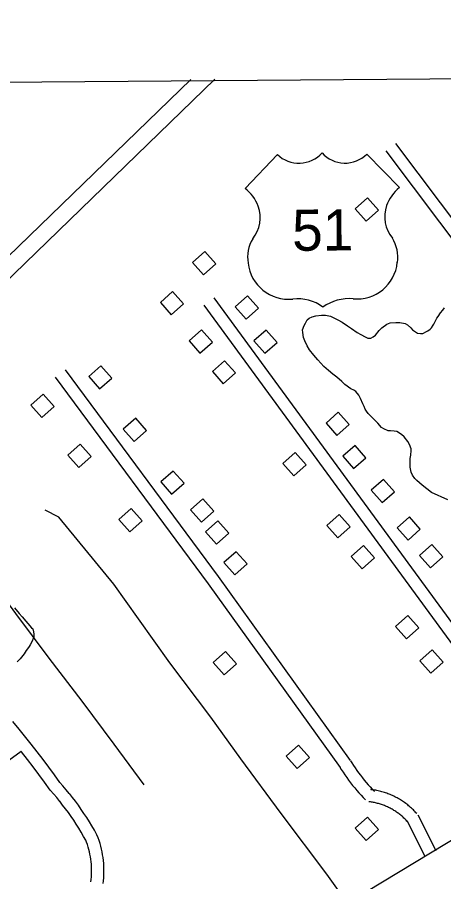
# Model space of a CAD drawing. Extents: x 3540316 to 3578335, y 553172 to 578787.
# Drawn here: x 3555638 to 3556674, y 574901 to 577000 of the extents above; entities that cross this region are included whole.
import ezdxf

# ---------------------------------------------------------------- set-up
doc = ezdxf.new("R2010")
doc.units = 0
for name, color, linetype in [('V-BLDG-OTLN', 7, 'Continuous'), ('V-GRID-FRAM', 7, 'Continuous'), ('V-ROAD-CNTR', 7, 'Continuous'), ('V-ROAD-IDEN', 7, 'Continuous'), ('V-SITE-VEGE', 7, 'Continuous'), ('V-TOPO-SHOR', 7, 'Continuous')]:
    doc.layers.add(name, color=color, linetype=linetype)

msp = doc.modelspace()

# ---------------------------------------------------------------- linework, layer by layer
at = {"layer": 'V-BLDG-OTLN'}
for points in [[(3556485.3, 576504.7), (3556515.2, 576531.2), (3556488.7, 576561.1), (3556458.7, 576534.6)], [(3556090.4, 576374.5), (3556120.4, 576401), (3556093.8, 576430.9), (3556063.9, 576404.4)], [(3556012.1, 576277.5), (3556042, 576304.1), (3556015.4, 576334), (3555985.5, 576307.5)], [(3556193.9, 576266.8), (3556223.9, 576293.3), (3556197.3, 576323.2), (3556167.4, 576296.7)], [(3556081.8, 576184.3), (3556111.8, 576210.8), (3556085.2, 576240.7), (3556055.3, 576214.2)], [(3556238.9, 576183.9), (3556268.8, 576210.4), (3556242.3, 576240.4), (3556212.3, 576213.8)], [(3556138.3, 576109.5), (3556168.3, 576136.1), (3556141.7, 576166), (3556111.8, 576139.5)], [(3555838, 576097.4), (3555867.9, 576123.9), (3555841.4, 576153.8), (3555811.5, 576127.3)], [(3555697.9, 576028), (3555727.8, 576054.5), (3555701.3, 576084.5), (3555671.3, 576057.9)], [(3556414.3, 575984.3), (3556444.2, 576010.8), (3556417.7, 576040.7), (3556387.8, 576014.2)], [(3555922.2, 575969.9), (3555952.1, 575996.4), (3555925.6, 576026.4), (3555895.6, 575999.8)], [(3555787.4, 575906.5), (3555817.3, 575933), (3555790.8, 575962.9), (3555760.8, 575936.4)], [(3556454.9, 575903.8), (3556484.9, 575930.4), (3556458.3, 575960.3), (3556428.4, 575933.8)], [(3556309.8, 575886.7), (3556339.7, 575913.2), (3556313.2, 575943.2), (3556283.2, 575916.6)], [(3556013, 575841.7), (3556043, 575868.2), (3556016.4, 575898.1), (3555986.5, 575871.6)], [(3556523.9, 575821.3), (3556553.8, 575847.9), (3556527.3, 575877.8), (3556497.3, 575851.3)], [(3556085.4, 575773.7), (3556115.4, 575800.3), (3556088.8, 575830.2), (3556058.9, 575803.7)], [(3555911.2, 575750.3), (3555941.1, 575776.9), (3555914.6, 575806.8), (3555884.7, 575780.3)], [(3556416.6, 575736.2), (3556446.6, 575762.7), (3556420, 575792.6), (3556390.1, 575766.1)], [(3556586.9, 575730.5), (3556616.8, 575757), (3556590.3, 575786.9), (3556560.4, 575760.4)], [(3556121.7, 575720.5), (3556151.6, 575747), (3556125.1, 575777), (3556095.2, 575750.4)], [(3556166.1, 575645.7), (3556196, 575672.3), (3556169.5, 575702.2), (3556139.5, 575675.7)], [(3556475.6, 575660.6), (3556505.5, 575687.2), (3556479, 575717.1), (3556449, 575690.6)], [(3556641.5, 575663.3), (3556671.4, 575689.8), (3556644.9, 575719.7), (3556615, 575693.2)], [(3556583.3, 575490.4), (3556613.2, 575516.9), (3556586.7, 575546.9), (3556556.7, 575520.3)], [(3556140.7, 575403.5), (3556170.6, 575430), (3556144, 575459.9), (3556114.1, 575433.4)], [(3556642.2, 575407.3), (3556672.2, 575433.9), (3556645.6, 575463.8), (3556615.7, 575437.3)], [(3556317.8, 575175.8), (3556347.7, 575202.3), (3556321.2, 575232.3), (3556291.2, 575205.7)], [(3556485, 575000.9), (3556514.9, 575027.5), (3556488.4, 575057.4), (3556458.5, 575030.8)]]:
    msp.add_lwpolyline(points, close=True, dxfattribs=at)
at = {"layer": 'V-GRID-FRAM'}
for points in [[(3544387.2, 576756), (3576013, 576999.8), (3576161.1, 558817.2), (3544519.4, 558573.3), (3544387.2, 576756)], [(3544387.2, 576756), (3576013, 576999.8)]]:
    msp.add_lwpolyline(points, dxfattribs=at)
at = {"layer": 'V-ROAD-CNTR'}
for points in [[(3556059.6, 576849.1), (3555248.7, 576063.5), (3553492.5, 574335)], [(3556117.7, 576849.5), (3555276.7, 576034.8), (3553520.7, 574306.4)], [(3557474.2, 575475.1), (3556557.5, 576693.2)], [(3557448.5, 575459.5), (3556533.5, 576675.2)], [(3556115.3, 576318.4), (3556960.7, 575164.1)], [(3556091.1, 576300.7), (3556936.5, 575146.3)], [(3555754.2, 576143.7), (3556126.1, 575641.7), (3556446.5, 575195.3)], [(3555730.1, 576125.8), (3556101.9, 575624), (3556422.1, 575177.8)], [(3558125.7, 575871.4), (3557699.7, 575612.4), (3556948.6, 575155.2), (3555833.4, 574482.3)], [(3555872.2, 575623.6), (3555739.2, 575785.8), (3555706.2, 575803)], [(3556440.2, 574848.4), (3556389.8, 574919), (3556278.9, 575066.4), (3556181.3, 575199.2), (3556108.4, 575300.5), (3556008.4, 575432.1), (3555932.5, 575539.3), (3555872.2, 575623.6)], [(3555764.5, 575115), (3555756.9, 575124.2), (3555749.1, 575133.3), (3555741.8, 575141.6), (3555728.5, 575160), (3555714.6, 575178.8), (3555700.6, 575197.6), (3555686.4, 575216.3), (3555672, 575234.8), (3555662.1, 575247.2), (3555642.7, 575271.4), (3555627.7, 575289.5)], [(3555647.6, 575217.2), (3555617.5, 575195.2), (3555575.7, 575164.7), (3555533.8, 575134.4), (3555491.7, 575104.3), (3555465.2, 575085.2)], [(3555741.3, 575095.9), (3555733.9, 575104.9), (3555726.5, 575113.6), (3555718.3, 575122.8), (3555704.3, 575142.3), (3555690.5, 575161), (3555676.7, 575179.5), (3555662.6, 575197.9), (3555648.4, 575216.2), (3555647.1, 575217.8)], [(3556421.5, 575178.7), (3556425, 575173.1), (3556429.3, 575166.5), (3556433.7, 575160), (3556438.2, 575153.6), (3556442.8, 575147.2), (3556447.6, 575140.8), (3556452.5, 575134.6), (3556457.4, 575128.5), (3556462.5, 575122.5), (3556467.7, 575116.5), (3556473, 575110.7), (3556478.4, 575104.9), (3556483.8, 575099.3)], [(3556447, 575194.5), (3556450.2, 575189.3), (3556454.3, 575183.1), (3556458.4, 575177), (3556462.7, 575171), (3556467, 575165), (3556471.4, 575159.2), (3556476, 575153.3), (3556480.6, 575147.6), (3556485.3, 575142), (3556490.2, 575136.4), (3556495.1, 575130.9), (3556500.1, 575125.5), (3556505.3, 575120.2)], [(3555846.6, 574896.2), (3555847.4, 574903.2), (3555848.1, 574910.2), (3555848.5, 574917.2), (3555848.7, 574924.3), (3555848.7, 574931.3), (3555848.5, 574938.3), (3555848, 574945.4), (3555847.4, 574952.4), (3555846.5, 574959.4), (3555845.4, 574966.4), (3555844.1, 574973.3), (3555842.6, 574980.2), (3555840.9, 574987), (3555839, 574993.8), (3555836.8, 575000.5), (3555834.5, 575007.2), (3555831.7, 575014.5), (3555825.4, 575025.8), (3555819.3, 575036.2), (3555813.1, 575046.4), (3555806.7, 575056.6), (3555800.1, 575066.6), (3555793.3, 575076.5), (3555786.4, 575086.3), (3555779.3, 575096), (3555772, 575105.5), (3555764.6, 575114.8)], [(3556608.3, 575066.1), (3556606.3, 575068.4), (3556604.2, 575070.6), (3556602.1, 575072.8), (3556599.9, 575075), (3556597.7, 575077.2), (3556595.4, 575079.2), (3556593.2, 575081.3), (3556590.8, 575083.3), (3556588.5, 575085.3), (3556586.1, 575087.3), (3556583.7, 575089.1), (3556581.3, 575091), (3556578.7, 575092.8), (3556576.2, 575094.6), (3556573.7, 575096.3), (3556571.1, 575098), (3556568.5, 575099.6), (3556565.9, 575101.2), (3556563.2, 575102.8), (3556560.5, 575104.2), (3556557.8, 575105.7), (3556555, 575107.1), (3556552.3, 575108.5), (3556549.5, 575109.8), (3556546.7, 575111), (3556543.9, 575112.2), (3556541, 575113.4), (3556538.2, 575114.5), (3556535.2, 575115.6), (3556532.4, 575116.6), (3556529.5, 575117.5), (3556526.5, 575118.4), (3556523.5, 575119.3), (3556520.6, 575120.1), (3556517.6, 575120.8), (3556514.6, 575121.5), (3556511.6, 575122.2), (3556508.6, 575122.8), (3556505.5, 575123.3), (3556502.5, 575123.8), (3556499.4, 575124.2), (3556497, 575124.5), (3556497.4, 575124.5)], [(3555816.8, 574900.3), (3555817.6, 574906.3), (3555818.1, 574912.4), (3555818.5, 574918.6), (3555818.7, 574924.7), (3555818.7, 574930.8), (3555818.5, 574936.9), (3555818.1, 574943.1), (3555817.5, 574949.2), (3555816.8, 574955.2), (3555815.8, 574961.3), (3555814.7, 574967.3), (3555813.4, 574973.3), (3555811.9, 574979.3), (3555810.2, 574985.1), (3555808.4, 574991), (3555806.4, 574996.8), (3555804.4, 575001.7), (3555799.3, 575010.9), (3555793.5, 575020.8), (3555787.6, 575030.6), (3555781.5, 575040.3), (3555775.2, 575049.9), (3555768.7, 575059.4), (3555762.1, 575068.7), (3555755.3, 575077.9), (3555748.3, 575087), (3555741.1, 575096.1)], [(3556585.9, 575046.2), (3556584.1, 575048.1), (3556582.4, 575050), (3556580.6, 575051.8), (3556578.8, 575053.7), (3556577, 575055.4), (3556575.1, 575057.2), (3556573.2, 575058.9), (3556571.3, 575060.5), (3556569.4, 575062.2), (3556567.4, 575063.8), (3556565.3, 575065.4), (3556563.3, 575066.9), (3556561.3, 575068.4), (3556559.2, 575069.9), (3556557.1, 575071.3), (3556554.9, 575072.7), (3556552.8, 575074.1), (3556550.6, 575075.4), (3556548.4, 575076.7), (3556546.1, 575077.9), (3556543.9, 575079.1), (3556541.6, 575080.3), (3556539.3, 575081.4), (3556537, 575082.5), (3556534.7, 575083.5), (3556532.3, 575084.5), (3556530, 575085.5), (3556527.6, 575086.4), (3556525.2, 575087.3), (3556522.8, 575088.1), (3556520.3, 575088.9), (3556517.9, 575089.7), (3556515.5, 575090.4), (3556513, 575091.1), (3556510.5, 575091.7), (3556508.1, 575092.2), (3556505.5, 575092.8), (3556503, 575093.3), (3556500.6, 575093.7), (3556498, 575094.1), (3556495.5, 575094.5), (3556492.4, 575094.9), (3556491.8, 575095)], [(3556583.7, 575049.3), (3556628, 574963)], [(3556610.4, 575063), (3556654.7, 574976.7)]]:
    msp.add_lwpolyline(points, dxfattribs=at)
at = {"layer": 'V-ROAD-IDEN'}
for p, q in [((3556191.3, 576584.4), (3556269.8, 576666.8)), ((3556191.3, 576584.4), (3556269.8, 576666.8)), ((3556486.8, 576667.6), (3556566.3, 576586.2)), ((3556566.3, 576586.2), (3556486.8, 576667.6)), ((3556191.3, 576584.4), (3556191.3, 576584.4))]:
    msp.add_line(p, q, dxfattribs=at)
for centre, major_axis, start_param, end_param in [((3556322, 576720.5), (0.6, -75), 5.502702, 7.121811), ((3556322, 576720.5), (0.6, -75), 5.502702, 7.121811), ((3556434, 576720.8), (-0.6, 75), 2.291842, 3.917604), ((3556434, 576720.8), (-0.6, 75), 2.291842, 3.917604), ((3556136.5, 576510.3), (-0.7, 92.2), 5.045266, 5.638568), ((3556136.5, 576510.3), (-0.7, 92.2), 5.045266, 5.638568), ((3556621.8, 576512.6), (0.7, -92.2), 3.781672, 4.374974), ((3556621.8, 576512.6), (0.7, -92.2), 3.781672, 4.374974), ((3556146.6, 576513.5), (-0.6, 81.6), 4.021008, 5.049788), ((3556146.6, 576513.5), (-0.6, 81.6), 4.021008, 5.049788), ((3556611.7, 576515.7), (0.6, -81.6), 4.370452, 5.399232), ((3556611.7, 576515.7), (0.6, -81.6), 4.370452, 5.399232), ((3556283.7, 576417.3), (0.7, -86.5), 4.163028, 4.868958), ((3556283.7, 576417.3), (0.7, -86.5), 4.163028, 4.868958), ((3556475.7, 576418), (-0.7, 86.5), 4.551282, 5.257212), ((3556475.7, 576418), (-0.7, 86.5), 4.551282, 5.257212), ((3556296.6, 576414), (-0.8, 98.8), 1.672766, 3.238327), ((3556296.6, 576414), (-0.8, 98.8), 1.672766, 3.238327), ((3556462.8, 576414.6), (0.8, -98.8), 6.181885, 7.747479), ((3556462.8, 576414.6), (0.8, -98.8), 6.181885, 7.747479), ((3556318.5, 576210.7), (-0.8, 105.6), 5.646836, 6.385311), ((3556318.5, 576210.7), (-0.8, 105.6), 5.646836, 6.385311), ((3556443.2, 576211), (0.8, -105.6), 3.034929, 3.773404), ((3556443.2, 576211), (0.8, -105.6), 3.034929, 3.773404)]:
    msp.add_ellipse(centre, major_axis=major_axis, ratio=0.99789, start_param=start_param, end_param=end_param, dxfattribs=at)
at = {"layer": 'V-SITE-VEGE'}
for points in [[(3556653.5, 576263.1), (3556656.7, 576269.2), (3556659.9, 576273.6), (3556665.8, 576282.4), (3556671.1, 576288.5), (3556675.4, 576294)], [(3556683.7, 575827.8), (3556644.1, 575846.3), (3556620.9, 575864), (3556608.2, 575874.8), (3556603.8, 575880.2), (3556598.2, 575888.3), (3556594.8, 575895.3), (3556592.5, 575907.3), (3556592.2, 575928.6), (3556593.7, 575936.3), (3556594.6, 575947.7), (3556594.6, 575951.6), (3556590.6, 575962.4), (3556586.7, 575970), (3556577.2, 575981.3), (3556571.1, 575986.7), (3556560.1, 575993.7), (3556553, 575995.2), (3556544.8, 575995.6), (3556538.8, 575995.5), (3556528.3, 576000.3), (3556522.8, 576004.1), (3556513.4, 576014.3), (3556506.7, 576021.3), (3556495.7, 576032.1), (3556490.1, 576038), (3556486.2, 576043.4), (3556482.9, 576048.3), (3556480.6, 576054.8), (3556477.2, 576061.3), (3556471.6, 576074.3), (3556467.1, 576082.4), (3556459.9, 576091.1), (3556455.5, 576094.8), (3556448.3, 576098), (3556433.4, 576108.2), (3556426.2, 576115.2), (3556414.1, 576125.9), (3556404.7, 576133.4), (3556394.2, 576142), (3556382.6, 576152.2), (3556367.6, 576168.4), (3556358.2, 576179.2), (3556347.6, 576192.7), (3556342, 576201.9), (3556336.4, 576213.8), (3556333, 576222), (3556331.2, 576234.5), (3556331.1, 576241.1), (3556334.7, 576251.5), (3556337.9, 576257.5), (3556342.2, 576265.2), (3556347, 576269.1), (3556354.1, 576272.5), (3556363.3, 576274.8), (3556377, 576276.7), (3556386.8, 576276.8), (3556398.9, 576273.7), (3556405.4, 576271.1), (3556416.5, 576265.2), (3556426.9, 576259.9), (3556440.1, 576250.8), (3556449.5, 576243.8), (3556463.3, 576234.7), (3556472.1, 576229.4), (3556482.6, 576223.6), (3556489.2, 576220.9), (3556496.8, 576220.5), (3556502.2, 576223.8), (3556507.6, 576228.3), (3556516.8, 576239.3), (3556523.2, 576245.4), (3556535.1, 576254.9), (3556543.2, 576258.3), (3556557.4, 576259), (3556566.7, 576258.6), (3556579.9, 576256.6), (3556585.9, 576252.9), (3556593.7, 576245.9), (3556597.5, 576241), (3556604.7, 576236.2), (3556610.2, 576233), (3556617.3, 576232), (3556623.3, 576232.1), (3556631.5, 576236.6), (3556635.3, 576238.8), (3556640.7, 576242.7), (3556643.9, 576245.5), (3556648.2, 576252.1), (3556649.8, 576254.9), (3556652.4, 576259.8), (3556653.5, 576263.1)], [(3555631.3, 575565.5), (3555642.4, 575552.5), (3555650.2, 575544.4), (3555672.9, 575516.9), (3555675.7, 575514.8), (3555677.4, 575507.7), (3555678.1, 575501.7), (3555678.2, 575494.6), (3555672.9, 575482), (3555669.2, 575475.9), (3555667, 575472), (3555663.3, 575466.5), (3555659.5, 575462.1), (3555654.7, 575453.8), (3555645.1, 575441.7), (3555637.5, 575434.5)]]:
    msp.add_lwpolyline(points, dxfattribs=at)
at = {"layer": 'V-TOPO-SHOR'}
msp.add_lwpolyline([(3555946.4, 575135.7), (3555873.5, 575234.6), (3555795.8, 575339.3), (3555715.8, 575443.5), (3555634.4, 575552.3), (3555546.5, 575671.7), (3555459.2, 575786.3), (3555423.1, 575826.6), (3555404.6, 575845.9)], dxfattribs=at)

# ---------------------------------------------------------------- texts
at = {"layer": 'V-ROAD-IDEN'}
msp.add_text('51', height=100, rotation=0.4506, dxfattribs=at).set_placement((3556305.9, 576432.7))

doc.saveas('drawing.dxf')
